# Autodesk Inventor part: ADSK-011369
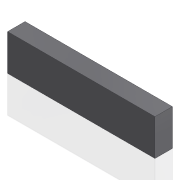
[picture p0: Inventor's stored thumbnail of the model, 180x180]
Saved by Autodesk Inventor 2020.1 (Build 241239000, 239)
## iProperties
Created: 1999-12
Part Number: ADSK-011369
Material: Acier doux
Document SubType Name: Modeling
Designer: sspink
Density: 7.86 g/cm^3
Appearance: Metal-Steel(Polish)
Mass: 29.9466 g
Surface Area: 20.296 cm^2
Volume: 3.81 cm^3
Control State: 0
Checked Out: False
Master: False
Shininess: 0.0
Length Units: 11269
Angle Units: 11279
Time Units: 11290
Mass Units: 11283
Length Display Precision: 3
Angle Display Precision: 2
Compacted: True
Cutlength: 2
Material Desc: FLAT,HRS,0.250X0.500
Material_Number: A084325
Dimensions: 50,8x12,5x6 mm
Mass: 0,03 kg
DocNumber: ADSK-011369.ipt
Folder: 01 - Themengebiete\Simplification\01 - Packaging machine\
VDS_Category: 3D Komponenten
Density: 0.0
Volumn: 0.0
Area: 0.0
PropertySet Name: Model Information
Author: sspink
Revision Number: -
Title: support
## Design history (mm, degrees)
node "Solide1"
  node "Extrusion1" dims "d2" = 6, "d3" = 0
sketch "Sketch1"
  geometry: L1 (-50.8, -12.5)-(0, -12.5); L2 (0, -12.5)-(0, 0); L3 (0, 0)-(-50.8, 0); L4 (-50.8, 0)-(-50.8, -12.5); 1 further point
  constraints: 8 end point, 2 parallel, 1 coincident, 1 horizontal, 1 perpendicular
  dimensions: "d0" = 50.8 distance of L2.end L3.end; "d1" = 12.5 distance of L3.end L1.start
node "Corps solides"
node "Corps surfaciques"
